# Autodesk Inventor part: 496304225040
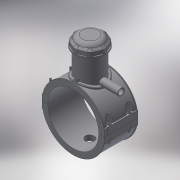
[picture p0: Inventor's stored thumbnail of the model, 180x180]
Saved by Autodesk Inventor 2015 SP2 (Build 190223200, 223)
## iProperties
Created: 2017-07
Part Number: 496304225040
Material: Generic
Description: PLASSON TAPPING SADDLE 225x40
Document SubType Name: Modeling
Designer: KIM
Mass: 1618.26 g
Surface Area: 3499.16 cm^2
Volume: 1618.26 cm^3
Density: 1 g/cm^3
Appearance: Default
Author: KIM
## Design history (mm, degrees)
derived "496304.ipt"
feature "Solid1::496304.ipt"
feature "Solid2::496304.ipt"
feature "Solid4::496304.ipt"
feature "Solid5::496304.ipt"
tag "TaggingFeature1" dims "B_" = 227
body "Solid1"
body "Solid2"
other parameters: "d_" = 225, "L_" = 176, "d_t" = 6, "H_2" = 177, "H_" = 142, "d1" = 256.5, "d148" = 3.375, "d160" = 3.375, "d169" = 3.375, "d192" = 6.3, "d0" = 225, "d2" = 295.1, "d3" = 56.25, "d4" = 176, "d5" = 0, "d6" = 0.1, "d8" = 0, "d19" = 6, "d20" = 6, "d21" = 105.6, "d23" = 0, "d24" = 52.8, "d26" = 0, "d29" = 3, "d30" = 75, "d31" = 6, "d32" = 0, "d33" = 0, "d34" = 0.6, "d40" = 133.38, "d43" = 0, "d45" = 0, "d47" = 233.85, "d70" = 15, "d72" = 0, "d73" = 6, "d75" = 5, "d76" = 0, "d77" = 11.25, "d78" = 142.5, "d79" = 15, "d80" = 70.4, "d82" = 5 deg, "d84" = 4, "d85" = 14, "d86" = 0, "d87" = 3, "d88" = 0, "d89" = 1, "d90" = 1, "d91" = 140.8, "d92" = 0, "d93" = 0.5, "d94" = 118.42105, "d96" = 261.63, "d97" = 3.52, "d98" = 0, "d102" = 2.25, "d120" = 140 deg, "d121" = 24.228, "d122" = 20 deg, "d123" = 513, "d124" = 153.9, "d126" = 0, "d143" = 231.75, "d145" = 24.23077, "d149" = 3.375, "d150" = 26.65385, "d153" = 176, "d154" = 0, "d156" = 128.25, "d157" = 160 deg, "d159" = 6.3, "d161" = 3.375, "d162" = 105.6, "d163" = 0, "d164" = 112.5, "d167" = 22.5, "d168" = 125.12195, "d170" = 3.375, "d172" = 0, "d173" = 1, "d175" = 112.5, "d176" = 20 deg, "d177" = 15.75, "d178" = 31.5, "d180" = 0, "d183" = 12.6, "d184" = 12.6, "d185" = 57.2, "d186" = 57.2, "d187" = 128.25, "d188" = 9.45, "d189" = 15.75, "d190" = 0, "d191" = 192.375, "d193" = 6.3, "d194" = 6.16, "d195" = 90 deg, "d197" = 0, "d199" = 0, "d200" = 15.75, "d202" = 0, "d203" = 177, "d204" = 85.5, "d205" = 63, "d206" = 76.5, "d207" = 132.75, "d208" = 138.06, "d209" = 164.61, "d210" = 77.4, "d212" = 72, "d213" = 36, "d216" = 0, "d217" = 22.5, "d218" = 22.5, "d219" = 4.5, "d222" = 225, "d224" = 0, "d230" = 4.5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
